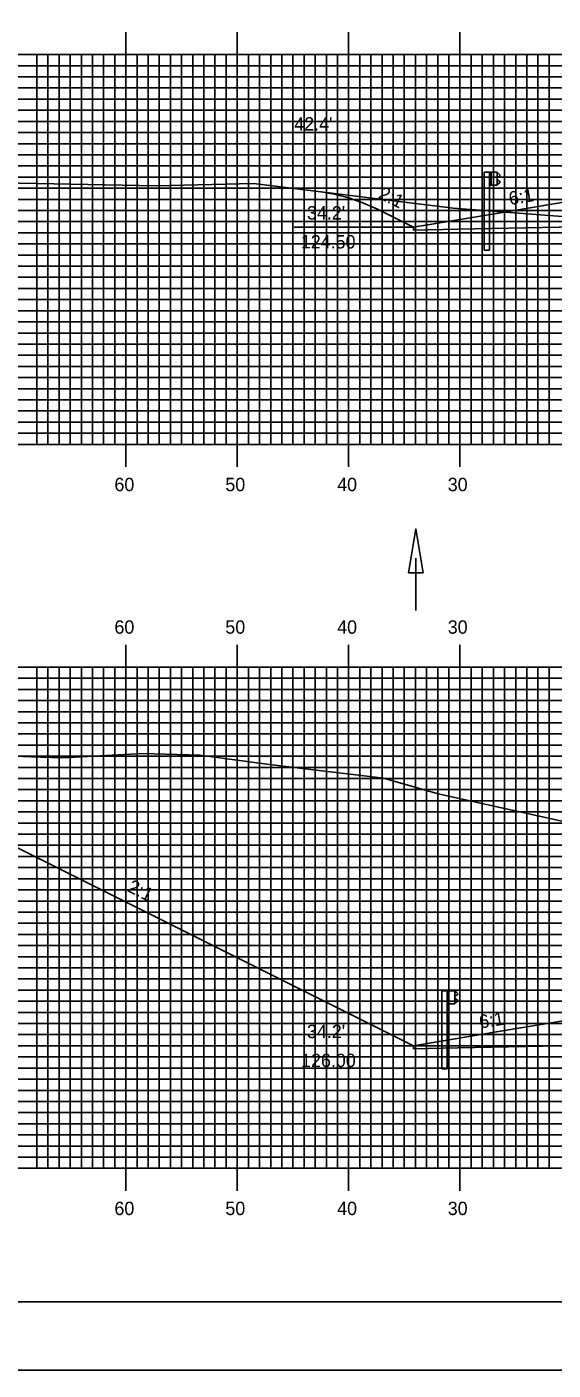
# Model space of a CAD drawing. Extents: x 1785402 to 1785745, y 442591 to 442811.
# Drawn here: x 1785498.6 to 1785545.9, y 442590.5 to 442711.2 of the extents above; entities that cross this region are included whole.
import ezdxf

# ---------------------------------------------------------------- set-up
doc = ezdxf.new("R2010")
doc.units = 0
for name, color, linetype in [('ANNOTATION', 7, 'Continuous'), ('BORDER', 7, 'Continuous'), ('D_Drainage_Ditch_Line', 7, 'Continuous'), ('D_Guardrail_Beam_Lt', 7, 'Continuous'), ('D_Roadway_SlopeLines', 7, 'Continuous'), ('D_Roadway_SubGrade', 7, 'Continuous'), ('D_Text_Standard', 7, 'Continuous'), ('H_V ANNOTATION', 7, 'Continuous'), ('MAJOR', 7, 'Continuous'), ('MINOR', 7, 'Continuous'), ('PDRAIN', 7, 'Continuous'), ('PLOT BOUNDARY', 7, 'Continuous'), ('S_Roadway_Centerline', 7, 'Continuous')]:
    doc.layers.add(name, color=color, linetype=linetype)

msp = doc.modelspace()

# ---------------------------------------------------------------- linework, layer by layer
at = {"layer": 'BORDER'}
msp.add_lwpolyline([(1785417.94, 442596.67), (1785737.94, 442596.67), (1785737.94, 442806.67), (1785417.94, 442806.67)], close=True, dxfattribs=at)
at = {"layer": 'D_Drainage_Ditch_Line'}
msp.add_line((1785533.58, 442663.46), (1785533.58, 442658.76), dxfattribs=at)
msp.add_lwpolyline([(1785534.24, 442662.15), (1785532.93, 442662.15), (1785533.58, 442666.08)], close=True, dxfattribs=at)
at = {"layer": 'D_Guardrail_Beam_Lt'}
for p, q in [((1785539.71, 442698.11), (1785539.71, 442691.11)), ((1785540.18, 442698.11), (1785539.71, 442698.11)), ((1785540.87, 442698.11), (1785540.18, 442698.11)), ((1785540.18, 442698.11), (1785540.18, 442696.94)), ((1785540.24, 442698.11), (1785540.24, 442696.94)), ((1785540.34, 442698.11), (1785540.34, 442696.94)), ((1785540.87, 442696.94), (1785540.87, 442698.11)), ((1785540.87, 442698.03), (1785540.94, 442698.01)), ((1785540.87, 442697.56), (1785540.87, 442697.49)), ((1785541.1, 442697.76), (1785540.9, 442697.63)), ((1785540.9, 442697.43), (1785541.1, 442697.29)), ((1785540.96, 442698.01), (1785541.1, 442697.91)), ((1785541.1, 442697.15), (1785540.96, 442697.05)), ((1785540.18, 442696.94), (1785540.87, 442696.94)), ((1785540.2, 442691.11), (1785540.2, 442696.94)), ((1785540.94, 442697.04), (1785540.87, 442697.03)), ((1785540.2, 442691.11), (1785539.71, 442691.11)), ((1785535.91, 442624.61), (1785535.91, 442617.61)), ((1785536.38, 442624.61), (1785535.91, 442624.61)), ((1785537.07, 442624.61), (1785536.38, 442624.61)), ((1785536.38, 442624.61), (1785536.38, 442623.44)), ((1785536.45, 442624.61), (1785536.45, 442623.44)), ((1785536.55, 442624.61), (1785536.55, 442623.44)), ((1785537.07, 442623.44), (1785537.07, 442624.61)), ((1785537.07, 442624.53), (1785537.14, 442624.51)), ((1785537.14, 442623.54), (1785537.07, 442623.53)), ((1785537.08, 442624.06), (1785537.08, 442623.99)), ((1785537.3, 442624.26), (1785537.11, 442624.13)), ((1785537.11, 442623.93), (1785537.3, 442623.79)), ((1785537.16, 442624.51), (1785537.3, 442624.41)), ((1785537.3, 442623.65), (1785537.16, 442623.55)), ((1785536.38, 442623.44), (1785537.07, 442623.44)), ((1785536.4, 442617.61), (1785536.4, 442623.44)), ((1785536.4, 442617.61), (1785535.91, 442617.61))]:
    msp.add_line(p, q, dxfattribs=at)
for centre, major_axis, start_param, end_param in [((1785540.95, 442697.56), (-0.0789, 0), 5.323254, 6.283185), ((1785540.95, 442697.49), (-0.0789, 0), 6.283185, 7.243116), ((1785540.93, 442697.97), (0.0417, 0), 0.959931, 1.376053), ((1785541.05, 442697.83), (0.0877, 0), 5.323254, 7.243116), ((1785541.05, 442697.22), (0.0877, 0), 5.323254, 7.243116), ((1785540.93, 442697.08), (0.0417, 0), 4.907132, 5.323254), ((1785537.15, 442624.06), (-0.0789, 0), 5.323254, 6.283185), ((1785537.15, 442623.99), (-0.0789, 0), 6.283185, 7.243116), ((1785537.14, 442624.47), (0.0417, 0), 0.959931, 1.376053), ((1785537.14, 442623.58), (0.0417, 0), 4.907132, 5.323254), ((1785537.25, 442624.33), (0.0877, 0), 5.323254, 7.243116), ((1785537.25, 442623.72), (0.0877, 0), 5.323254, 7.243116)]:
    msp.add_ellipse(centre, major_axis=major_axis, ratio=0.995501, start_param=start_param, end_param=end_param, dxfattribs=at)
at = {"layer": 'D_Roadway_SlopeLines'}
for p, q in [((1785533.36, 442692.9), (1785533.36, 442693.16)), ((1785537.36, 442692.98), (1785533.36, 442692.9))]:
    msp.add_line(p, q, dxfattribs=at)
for points in [[(1785533.36, 442693.16), (1785530.14, 442694.78), (1785528.89, 442695.34), (1785527.64, 442695.79), (1785526.39, 442696.12), (1785525.14, 442696.34)], [(1785547.54, 442695.53), (1785541.54, 442694.53), (1785533.36, 442693.16)], [(1785533.36, 442619.66), (1785484.2, 442644.25), (1785482.95, 442644.79), (1785481.7, 442645.17), (1785480.45, 442645.38), (1785479.2, 442645.42)], [(1785547.54, 442622.03), (1785541.54, 442621.03), (1785533.36, 442619.66)], [(1785537.36, 442619.48), (1785533.36, 442619.4), (1785533.36, 442619.67)]]:
    msp.add_lwpolyline(points, dxfattribs=at)
at = {"layer": 'D_Roadway_SubGrade'}
for points in [[(1785597.71, 442693.51), (1785579.54, 442693.87), (1785567.54, 442693.61), (1785555.54, 442693.35), (1785537.36, 442692.98)], [(1785597.71, 442620.01), (1785579.54, 442620.37), (1785567.54, 442620.11), (1785555.54, 442619.85), (1785537.36, 442619.48)]]:
    msp.add_lwpolyline(points, dxfattribs=at)
at = {"layer": 'MAJOR'}
for p, q in [((1785507.54, 442710.67), (1785507.54, 442708.67)), ((1785517.54, 442710.67), (1785517.54, 442708.67)), ((1785527.54, 442710.67), (1785527.54, 442708.67)), ((1785537.54, 442710.67), (1785537.54, 442708.67)), ((1785427.54, 442708.67), (1785707.54, 442708.67)), ((1785427.54, 442708.67), (1785707.54, 442708.67)), ((1785507.54, 442673.67), (1785507.54, 442708.67)), ((1785517.54, 442673.67), (1785517.54, 442708.67)), ((1785527.54, 442673.67), (1785527.54, 442708.67)), ((1785537.54, 442673.67), (1785537.54, 442708.67)), ((1785427.54, 442703.67), (1785707.54, 442703.67)), ((1785427.54, 442698.67), (1785707.54, 442698.67)), ((1785427.54, 442693.67), (1785707.54, 442693.67)), ((1785427.54, 442688.67), (1785707.54, 442688.67)), ((1785427.54, 442683.67), (1785707.54, 442683.67)), ((1785427.54, 442678.67), (1785707.54, 442678.67)), ((1785427.54, 442673.67), (1785707.54, 442673.67)), ((1785427.54, 442673.67), (1785707.54, 442673.67)), ((1785507.54, 442671.66), (1785507.54, 442673.67)), ((1785517.54, 442671.66), (1785517.54, 442673.67)), ((1785527.54, 442671.66), (1785527.54, 442673.67)), ((1785537.54, 442671.66), (1785537.54, 442673.67)), ((1785507.54, 442655.67), (1785507.54, 442653.67)), ((1785517.54, 442655.67), (1785517.54, 442653.67)), ((1785527.54, 442655.67), (1785527.54, 442653.67)), ((1785537.54, 442655.67), (1785537.54, 442653.67)), ((1785427.54, 442653.67), (1785707.54, 442653.67)), ((1785427.54, 442653.67), (1785707.54, 442653.67)), ((1785507.54, 442608.67), (1785507.54, 442653.67)), ((1785517.54, 442608.67), (1785517.54, 442653.67)), ((1785527.54, 442608.67), (1785527.54, 442653.67)), ((1785537.54, 442608.67), (1785537.54, 442653.67)), ((1785427.54, 442648.67), (1785707.54, 442648.67)), ((1785427.54, 442643.67), (1785707.54, 442643.67)), ((1785427.54, 442638.67), (1785707.54, 442638.67)), ((1785427.54, 442633.67), (1785707.54, 442633.67)), ((1785427.54, 442628.67), (1785707.54, 442628.67)), ((1785427.54, 442623.67), (1785707.54, 442623.67)), ((1785427.54, 442618.67), (1785707.54, 442618.67)), ((1785427.54, 442613.67), (1785707.54, 442613.67)), ((1785427.54, 442608.67), (1785707.54, 442608.67)), ((1785427.54, 442608.67), (1785707.54, 442608.67)), ((1785507.54, 442606.66), (1785507.54, 442608.67)), ((1785517.54, 442606.66), (1785517.54, 442608.67)), ((1785527.54, 442606.66), (1785527.54, 442608.67)), ((1785537.54, 442606.66), (1785537.54, 442608.67))]:
    msp.add_line(p, q, dxfattribs=at)
at = {"layer": 'MINOR'}
for p, q in [((1785499.54, 442673.67), (1785499.54, 442708.67)), ((1785500.54, 442673.67), (1785500.54, 442708.67)), ((1785501.54, 442673.67), (1785501.54, 442708.67)), ((1785502.54, 442673.67), (1785502.54, 442708.67)), ((1785503.54, 442673.67), (1785503.54, 442708.67)), ((1785504.54, 442673.67), (1785504.54, 442708.67)), ((1785505.54, 442673.67), (1785505.54, 442708.67)), ((1785506.54, 442673.67), (1785506.54, 442708.67)), ((1785508.54, 442673.67), (1785508.54, 442708.67)), ((1785509.54, 442673.67), (1785509.54, 442708.67)), ((1785510.54, 442673.67), (1785510.54, 442708.67)), ((1785511.54, 442673.67), (1785511.54, 442708.67)), ((1785512.54, 442673.67), (1785512.54, 442708.67)), ((1785513.54, 442673.67), (1785513.54, 442708.67)), ((1785514.54, 442673.67), (1785514.54, 442708.67)), ((1785515.54, 442673.67), (1785515.54, 442708.67)), ((1785516.54, 442673.67), (1785516.54, 442708.67)), ((1785518.54, 442673.67), (1785518.54, 442708.67)), ((1785519.54, 442673.67), (1785519.54, 442708.67)), ((1785520.54, 442673.67), (1785520.54, 442708.67)), ((1785521.54, 442673.67), (1785521.54, 442708.67)), ((1785522.54, 442673.67), (1785522.54, 442708.67)), ((1785523.54, 442673.67), (1785523.54, 442708.67)), ((1785524.54, 442673.67), (1785524.54, 442708.67)), ((1785525.54, 442673.67), (1785525.54, 442708.67)), ((1785526.54, 442673.67), (1785526.54, 442708.67)), ((1785528.54, 442673.67), (1785528.54, 442708.67)), ((1785529.54, 442673.67), (1785529.54, 442708.67)), ((1785530.54, 442673.67), (1785530.54, 442708.67)), ((1785531.54, 442673.67), (1785531.54, 442708.67)), ((1785532.54, 442673.67), (1785532.54, 442708.67)), ((1785533.54, 442673.67), (1785533.54, 442708.67)), ((1785534.54, 442673.67), (1785534.54, 442708.67)), ((1785535.54, 442673.67), (1785535.54, 442708.67)), ((1785536.54, 442673.67), (1785536.54, 442708.67)), ((1785538.54, 442673.67), (1785538.54, 442708.67)), ((1785539.54, 442673.67), (1785539.54, 442708.67)), ((1785540.54, 442673.67), (1785540.54, 442708.67)), ((1785541.54, 442673.67), (1785541.54, 442708.67)), ((1785542.54, 442673.67), (1785542.54, 442708.67)), ((1785543.54, 442673.67), (1785543.54, 442708.67)), ((1785544.54, 442673.67), (1785544.54, 442708.67)), ((1785545.54, 442673.67), (1785545.54, 442708.67)), ((1785427.54, 442707.67), (1785707.54, 442707.67)), ((1785427.54, 442706.67), (1785707.54, 442706.67)), ((1785427.54, 442705.67), (1785707.54, 442705.67)), ((1785427.54, 442704.67), (1785707.54, 442704.67)), ((1785427.54, 442702.67), (1785707.54, 442702.67)), ((1785427.54, 442701.67), (1785707.54, 442701.67)), ((1785427.54, 442700.67), (1785707.54, 442700.67)), ((1785427.54, 442699.67), (1785707.54, 442699.67)), ((1785427.54, 442697.67), (1785707.54, 442697.67)), ((1785427.54, 442696.67), (1785707.54, 442696.67)), ((1785427.54, 442695.67), (1785707.54, 442695.67)), ((1785427.54, 442694.67), (1785707.54, 442694.67)), ((1785427.54, 442692.67), (1785707.54, 442692.67)), ((1785427.54, 442691.67), (1785707.54, 442691.67)), ((1785427.54, 442690.67), (1785707.54, 442690.67)), ((1785427.54, 442689.67), (1785707.54, 442689.67)), ((1785427.54, 442687.67), (1785707.54, 442687.67)), ((1785427.54, 442686.67), (1785707.54, 442686.67)), ((1785427.54, 442685.67), (1785707.54, 442685.67)), ((1785427.54, 442684.67), (1785707.54, 442684.67)), ((1785427.54, 442682.67), (1785707.54, 442682.67)), ((1785427.54, 442681.67), (1785707.54, 442681.67)), ((1785427.54, 442680.67), (1785707.54, 442680.67)), ((1785427.54, 442679.67), (1785707.54, 442679.67)), ((1785427.54, 442677.67), (1785707.54, 442677.67)), ((1785427.54, 442676.67), (1785707.54, 442676.67)), ((1785427.54, 442675.67), (1785707.54, 442675.67)), ((1785427.54, 442674.67), (1785707.54, 442674.67)), ((1785499.54, 442608.67), (1785499.54, 442653.67)), ((1785500.54, 442608.67), (1785500.54, 442653.67)), ((1785501.54, 442608.67), (1785501.54, 442653.67)), ((1785502.54, 442608.67), (1785502.54, 442653.67)), ((1785503.54, 442608.67), (1785503.54, 442653.67)), ((1785504.54, 442608.67), (1785504.54, 442653.67)), ((1785505.54, 442608.67), (1785505.54, 442653.67)), ((1785506.54, 442608.67), (1785506.54, 442653.67)), ((1785508.54, 442608.67), (1785508.54, 442653.67)), ((1785509.54, 442608.67), (1785509.54, 442653.67)), ((1785510.54, 442608.67), (1785510.54, 442653.67)), ((1785511.54, 442608.67), (1785511.54, 442653.67)), ((1785512.54, 442608.67), (1785512.54, 442653.67)), ((1785513.54, 442608.67), (1785513.54, 442653.67)), ((1785514.54, 442608.67), (1785514.54, 442653.67)), ((1785515.54, 442608.67), (1785515.54, 442653.67)), ((1785516.54, 442608.67), (1785516.54, 442653.67)), ((1785518.54, 442608.67), (1785518.54, 442653.67)), ((1785519.54, 442608.67), (1785519.54, 442653.67)), ((1785520.54, 442608.67), (1785520.54, 442653.67)), ((1785521.54, 442608.67), (1785521.54, 442653.67)), ((1785522.54, 442608.67), (1785522.54, 442653.67)), ((1785523.54, 442608.67), (1785523.54, 442653.67)), ((1785524.54, 442608.67), (1785524.54, 442653.67)), ((1785525.54, 442608.67), (1785525.54, 442653.67)), ((1785526.54, 442608.67), (1785526.54, 442653.67)), ((1785528.54, 442608.67), (1785528.54, 442653.67)), ((1785529.54, 442608.67), (1785529.54, 442653.67)), ((1785530.54, 442608.67), (1785530.54, 442653.67)), ((1785531.54, 442608.67), (1785531.54, 442653.67)), ((1785532.54, 442608.67), (1785532.54, 442653.67)), ((1785533.54, 442608.67), (1785533.54, 442653.67)), ((1785534.54, 442608.67), (1785534.54, 442653.67)), ((1785535.54, 442608.67), (1785535.54, 442653.67)), ((1785536.54, 442608.67), (1785536.54, 442653.67)), ((1785538.54, 442608.67), (1785538.54, 442653.67)), ((1785539.54, 442608.67), (1785539.54, 442653.67)), ((1785540.54, 442608.67), (1785540.54, 442653.67)), ((1785541.54, 442608.67), (1785541.54, 442653.67)), ((1785542.54, 442608.67), (1785542.54, 442653.67)), ((1785543.54, 442608.67), (1785543.54, 442653.67)), ((1785544.54, 442608.67), (1785544.54, 442653.67)), ((1785545.54, 442608.67), (1785545.54, 442653.67)), ((1785427.54, 442652.67), (1785707.54, 442652.67)), ((1785427.54, 442651.67), (1785707.54, 442651.67)), ((1785427.54, 442650.67), (1785707.54, 442650.67)), ((1785427.54, 442649.67), (1785707.54, 442649.67)), ((1785427.54, 442647.67), (1785707.54, 442647.67)), ((1785427.54, 442646.67), (1785707.54, 442646.67)), ((1785427.54, 442645.67), (1785707.54, 442645.67)), ((1785427.54, 442644.67), (1785707.54, 442644.67)), ((1785427.54, 442642.67), (1785707.54, 442642.67)), ((1785427.54, 442641.67), (1785707.54, 442641.67)), ((1785427.54, 442640.67), (1785707.54, 442640.67)), ((1785427.54, 442639.67), (1785707.54, 442639.67)), ((1785427.54, 442637.67), (1785707.54, 442637.67)), ((1785427.54, 442636.67), (1785707.54, 442636.67)), ((1785427.54, 442635.67), (1785707.54, 442635.67)), ((1785427.54, 442634.67), (1785707.54, 442634.67)), ((1785427.54, 442632.67), (1785707.54, 442632.67)), ((1785427.54, 442631.67), (1785707.54, 442631.67)), ((1785427.54, 442630.67), (1785707.54, 442630.67)), ((1785427.54, 442629.67), (1785707.54, 442629.67)), ((1785427.54, 442627.67), (1785707.54, 442627.67)), ((1785427.54, 442626.67), (1785707.54, 442626.67)), ((1785427.54, 442625.67), (1785707.54, 442625.67)), ((1785427.54, 442624.67), (1785707.54, 442624.67)), ((1785427.54, 442622.67), (1785707.54, 442622.67)), ((1785427.54, 442621.67), (1785707.54, 442621.67)), ((1785427.54, 442620.67), (1785707.54, 442620.67)), ((1785427.54, 442619.67), (1785707.54, 442619.67)), ((1785427.54, 442617.67), (1785707.54, 442617.67)), ((1785427.54, 442616.67), (1785707.54, 442616.67)), ((1785427.54, 442615.67), (1785707.54, 442615.67)), ((1785427.54, 442614.67), (1785707.54, 442614.67)), ((1785427.54, 442612.67), (1785707.54, 442612.67)), ((1785427.54, 442611.67), (1785707.54, 442611.67)), ((1785427.54, 442610.67), (1785707.54, 442610.67)), ((1785427.54, 442609.67), (1785707.54, 442609.67))]:
    msp.add_line(p, q, dxfattribs=at)
at = {"layer": 'PDRAIN'}
for p, q in [((1785522.64, 442693.16), (1785533.36, 442693.16)), ((1785522.64, 442619.66), (1785533.36, 442619.66))]:
    msp.add_line(p, q, dxfattribs=at)
at = {"layer": 'PLOT BOUNDARY'}
msp.add_lwpolyline([(1785401.75, 442590.55), (1785741.75, 442590.55), (1785741.75, 442810.55), (1785401.75, 442810.55)], close=True, dxfattribs=at)
at = {"layer": 'S_Roadway_Centerline'}
for points in [[(1785427.54, 442700.39), (1785446.41, 442699.48), (1785447.49, 442699.44), (1785455.03, 442698.81), (1785467.38, 442697.7), (1785469.16, 442697.68), (1785471.57, 442697.7), (1785481.63, 442698.29), (1785489.68, 442697.53), (1785496.45, 442697.16), (1785510.26, 442696.88), (1785519.01, 442697.09), (1785536.92, 442694.88), (1785548.31, 442694.01), (1785553.52, 442693.96), (1785563.17, 442693.89), (1785574.43, 442693.48), (1785576.28, 442693.43), (1785594.5, 442691.22), (1785603.28, 442690.91), (1785609.96, 442691.19), (1785616.82, 442690.7), (1785633.18, 442689.06)], [(1785497.48, 442645.68), (1785499.86, 442645.6), (1785501.88, 442645.52), (1785509.05, 442645.9), (1785514.18, 442645.76), (1785520.19, 442644.95), (1785523.4, 442644.57), (1785530.68, 442643.7), (1785535.58, 442642.29), (1785551.17, 442638.85), (1785558.17, 442637.49), (1785566.61, 442636.56), (1785570.3, 442636.11), (1785573.3, 442636.06), (1785581.61, 442635.45), (1785591.46, 442634.32), (1785605.07, 442632.8), (1785616.65, 442632.21), (1785618.76, 442632.05), (1785638.22, 442629.56)]]:
    msp.add_lwpolyline(points, dxfattribs=at)

# ---------------------------------------------------------------- texts
at = {"layer": 'ANNOTATION'}
for s, rotation, p in [('2:1', 333.4349, (1785530.12, 442695.82)), ('6:1', 9.4623, (1785542.03, 442695.15)), ('2:1', 333.4349, (1785507.6, 442633.58)), ('6:1', 9.4623, (1785539.37, 442621.21))]:
    msp.add_text(s, height=1.2, rotation=rotation, dxfattribs=at).set_placement(p)
for s, p in [("34.2'", (1785523.8, 442693.86)), ('124.50', (1785523.25, 442691.26)), ("34.2'", (1785523.8, 442620.36)), ('126.00', (1785523.27, 442617.76))]:
    msp.add_text(s, height=1.2, dxfattribs=at).set_placement(p)
at = {"layer": 'D_Text_Standard'}
msp.add_text("42.4'", height=1.2, dxfattribs=at).set_placement((1785522.66, 442701.85))
at = {"layer": 'H_V ANNOTATION'}
for s, p in [('60', (1785506.51, 442669.47)), ('50', (1785516.47, 442669.47)), ('40', (1785526.51, 442669.47)), ('30', (1785536.44, 442669.47)), ('60', (1785506.51, 442656.67)), ('50', (1785516.47, 442656.67)), ('40', (1785526.51, 442656.67)), ('30', (1785536.44, 442656.67)), ('60', (1785506.51, 442604.47)), ('50', (1785516.47, 442604.47)), ('40', (1785526.51, 442604.47)), ('30', (1785536.44, 442604.47))]:
    msp.add_text(s, height=1.2, dxfattribs=at).set_placement(p)

doc.saveas('drawing.dxf')
